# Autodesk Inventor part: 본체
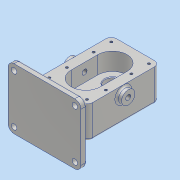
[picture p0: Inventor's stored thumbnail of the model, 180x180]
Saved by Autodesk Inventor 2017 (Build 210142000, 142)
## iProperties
Part Number: 본체
Material: 알루미늄 6061
Document SubType Name: Modeling
Designer: MRC
Density: 2.7 g/cm^3
Appearance: 알루미늄 - 평지
Mass: 1471.9 g
Surface Area: 819.891 cm^2
Volume: 545.148 cm^3
Author: MRC
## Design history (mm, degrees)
sketch "스케치1"
  geometry: L1 (-40, -60)-(40, -60); L2 (40, -60)-(40, 60); L3 (40, 60)-(-40, 60); L4 (-40, 60)-(-40, -60); L5 (-40, -60)-(40, 60); L6 (40, -60)-(-40, 60); 1 further point
  constraints: 12 end point, 2 midpoint, 2 parallel, 1 horizontal, 1 perpendicular
  dimensions: "d0" = 80 distance of L3.end L2.end; "d1" = 120 distance of L2.end L1.end
extrude "돌출1" new body sketch "스케치1" distance "d2" = 14; taper "d3" = 0 deg; dims "d6" = 39, "d7" = 0
sketch "스케치3"
  geometry: L1 (0, 22)-(0, -22); L2 (-24, 22)-(-24, -22); L3 (24, -22)-(24, 22); A1 r 24 centre (0, 22) between (24, 22) and (-24, 22); A2 r 24 centre (0, -22) between (-24, -22) and (24, -22); 4 further points
  constraints: 8 end point, 5 point on circle, 4 tangent, 2 centre point, 2 midpoint, 1 horizontal alignment, 1 parallel, 1 vertical, 1 vertical alignment
  dimensions: "d8" = 92 dimension on A2 A1; "d9" = 24 radius of A1
extrude "돌출2" cut sketch "스케치3" distance "d10" = 29; taper "d11" = 0 deg
sketch "스케치5"
  geometry: C1 r 19 at (0, 22); A1 r 24 centre (0, 22) between (24, 22) and (-24, 22) reference; 1 further point
  constraints: 1 centre point, 1 coincident
  dimensions: "d13" = 38 diameter of C1
extrude "돌출3" join sketch "스케치5" distance "d14" = 41; taper "d15" = 0 deg
sketch "스케치6"
  geometry: C1 r 19 at (0, 0) reference; C2 r 14 at (0, 0); 1 further point
  constraints: 1 centre point, 1 coincident
  dimensions: "d16" = 28 diameter of C2
extrude "돌출4" cut sketch "스케치6" distance "d17" = 7.3; taper "d18" = 0 deg
fillet "모깎기1" dims "d19" = 0.5
sketch "스케치7"
  geometry: C1 r 11 at (14, 60); 1 further point
  constraints: 1 centre point, 1 coincident
  dimensions: "d20" = 22 diameter of C1
extrude "돌출5" join sketch "스케치7" distance "d21" = 8; taper "d22" = 0 deg
hole "구멍1" diameter "d25" = 8.376; stored, may be unused: countersink angle "d29" = 90 deg, drill point angle "d31" = 118 deg; dims "d23" = 10, "d24" = 10, "d26" = 30, "d27" = 4, "d28" = 2, "d30" = 27.3
sketch "스케치8"
  geometry: A1 r 24 centre (0, 22) between (24, 22) and (-24, 22) reference; 1 further point
hole "구멍2" sketch "스케치8" at (0, 22) diameter "d33" = 17; stored, may be unused: countersink angle "d37" = 90 deg, drill point angle "d39" = 118 deg; dims "d34" = 20, "d35" = 25, "d36" = 15, "d38" = 27.3
sketch "스케치9"
  geometry: C1 r 12.5 at (0, -22); A1 r 24 centre (0, -22) between (-24, -22) and (24, -22) reference; 1 further point
  constraints: 1 centre point, 1 coincident
  dimensions: "d40" = 25 diameter of C1
extrude "돌출6" cut sketch "스케치9" distance "d41" = 15; taper "d42" = 0 deg
fillet "모깎기3" dims "d43" = 9
sketch "스케치10"
  geometry: A1 r 9 centre (-31, 51) between (-31, 60) and (-40, 51) reference; 2 further points
  constraints: 1 coincident
hole "구멍3" sketch "스케치10" at (-31, 51) diameter "d44" = 4.134; stored, may be unused: countersink angle "d48" = 90 deg, drill point angle "d50" = 118 deg; dims "d45" = 10, "d46" = 25, "d47" = 15, "d49" = 12
sketch "스케치11"
  geometry: C1 r 2.067 at (31, 51) reference; C2 r 2.067 at (-31, 51) reference; A1 r 9 centre (-31, 51) between (-31, 60) and (-40, 51) reference; A2 r 24 centre (0, -22) between (-24, -22) and (24, -22) reference; A3 r 24 centre (0, 22) between (24, 22) and (-24, 22) reference; 6 further points
  constraints: 3 horizontal alignment, 2 vertical alignment
  dimensions: "d54" = 29 distance of C2.centre point (-31, 22); "d55" = 29 distance of C1.centre point (31, 22)
hole "구멍4" sketch "스케치11" at (-31, 22), (31, 22), (33.067, -22), (-31, -22), (-46.329, 81.819) diameter "d56" = 4.134; stored, may be unused: countersink angle "d60" = 90 deg, drill point angle "d62" = 118 deg; dims "d57" = 10, "d58" = 25, "d59" = 15, "d61" = 12
node "작업 평면1"
sketch "스케치12"
  geometry: L1 (60, 44)-(-60, 44); L2 (-60, 44)-(-60, -56); L3 (-60, -56)-(60, -56); L4 (60, -56)-(60, 44); L5 (-19, -56)-(19, -56) reference; 2 further points
  constraints: 8 end point, 2 parallel, 1 collinear, 1 horizontal, 1 midpoint, 1 perpendicular, 1 vertical alignment
  dimensions: "d64" = 100 distance of L3.end L1.start; "d65" = 120 distance of L1.start L1.end
extrude "돌출7" join sketch "스케치12" distance "d66" = 10; taper "d67" = 0 deg
fillet "모깎기4" dims "d68" = 10
chamfer "모따기1" distance "d72" = 0.7; stored, may be unused: second distance "d73" = 2, angle "d74" = 30 deg
sketch "스케치14"
  geometry: L1 (-60, 2.453)-(-80, 14); L2 (-80, 14)-(-80, -39); L3 (-80, -39)-(-60, -27.453); L4 (-60, -27.453)-(-60, 2.453); L5 (-90, -56)-(-80, -56) reference; L6 (-80, -46)-(-80, 34) reference; L7 (-60, -39)-(-60, 14) reference; 1 further point
  constraints: 8 end point, 2 collinear, 1 equal length, 1 parallel, 1 vertical
  dimensions: "d81" = 17 distance from line of L2.end L5; "d82" = 60 deg angle of L2 L3; "d83" = 53 distance of L1.end L2.end
extrude "돌출10" join sketch "스케치14" stored distance "d84" = 48; taper "d85" = 0 deg
sketch "스케치15"
  geometry: C1 r 4.5 at (-50, -34); C2 r 4.5 at (-50, 46); C3 r 4.5 at (50, 46); C4 r 4.5 at (50, -34); A1 r 10 centre (-50, 46) between (-50, 56) and (-60, 46) reference; A2 r 10 centre (-50, -34) between (-60, -34) and (-50, -44) reference; A3 r 10 centre (50, -34) between (50, -44) and (60, -34) reference; A4 r 10 centre (50, 46) between (60, 46) and (50, 56) reference; 1 further point
  constraints: 4 centre point, 4 coincident
  dimensions: "d86" = 9 diameter of C1; "d87" = 9 diameter of C2; "d88" = 9 diameter of C3; "d89" = 9 diameter of C4
extrude "돌출11" cut sketch "스케치15" distance "d90" = 48; taper "d91" = 0 deg
sketch "스케치16"
  geometry: L1 (-60, 46)-(-60, -34) reference; L2 (-50, -44)-(50, -44) reference; 2 further points
  constraints: 1 other
  dimensions: "d102" = 60 distance from line of L1 point (0, -34); "d103" = 10 distance from line of L2 point (0, -34)
feature "엠보싱1" sketch "스케치16" dims "d0" = 80, "d1" = 120, "d92" = 0.5, "d93" = 0
chamfer "모따기2" distance "d94" = 1; stored, may be unused: second distance "d95" = 2, angle "d96" = 30 deg
fillet "모깎기5" dims "d97" = 3
fillet "모깎기6" dims "d98" = 3
fillet "모깎기7" dims "d99" = 3
fillet "모깎기8" dims "d100" = 3
node "솔리드1"
mirror "미러1"
pattern_linear "직사각형 패턴1" dims "d53" = 62
mirror "미러2"
